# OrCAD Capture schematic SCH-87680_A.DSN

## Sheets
1 4. BRKT-Sensors: size B; title: FRDM-STBA-A8961; rev: A; company: Freescale Semiconductor; note: SCH-87680 PDF: SPF-87680; note: 6501 William Cannon Drive West; note: Austin, TX 78735-8598
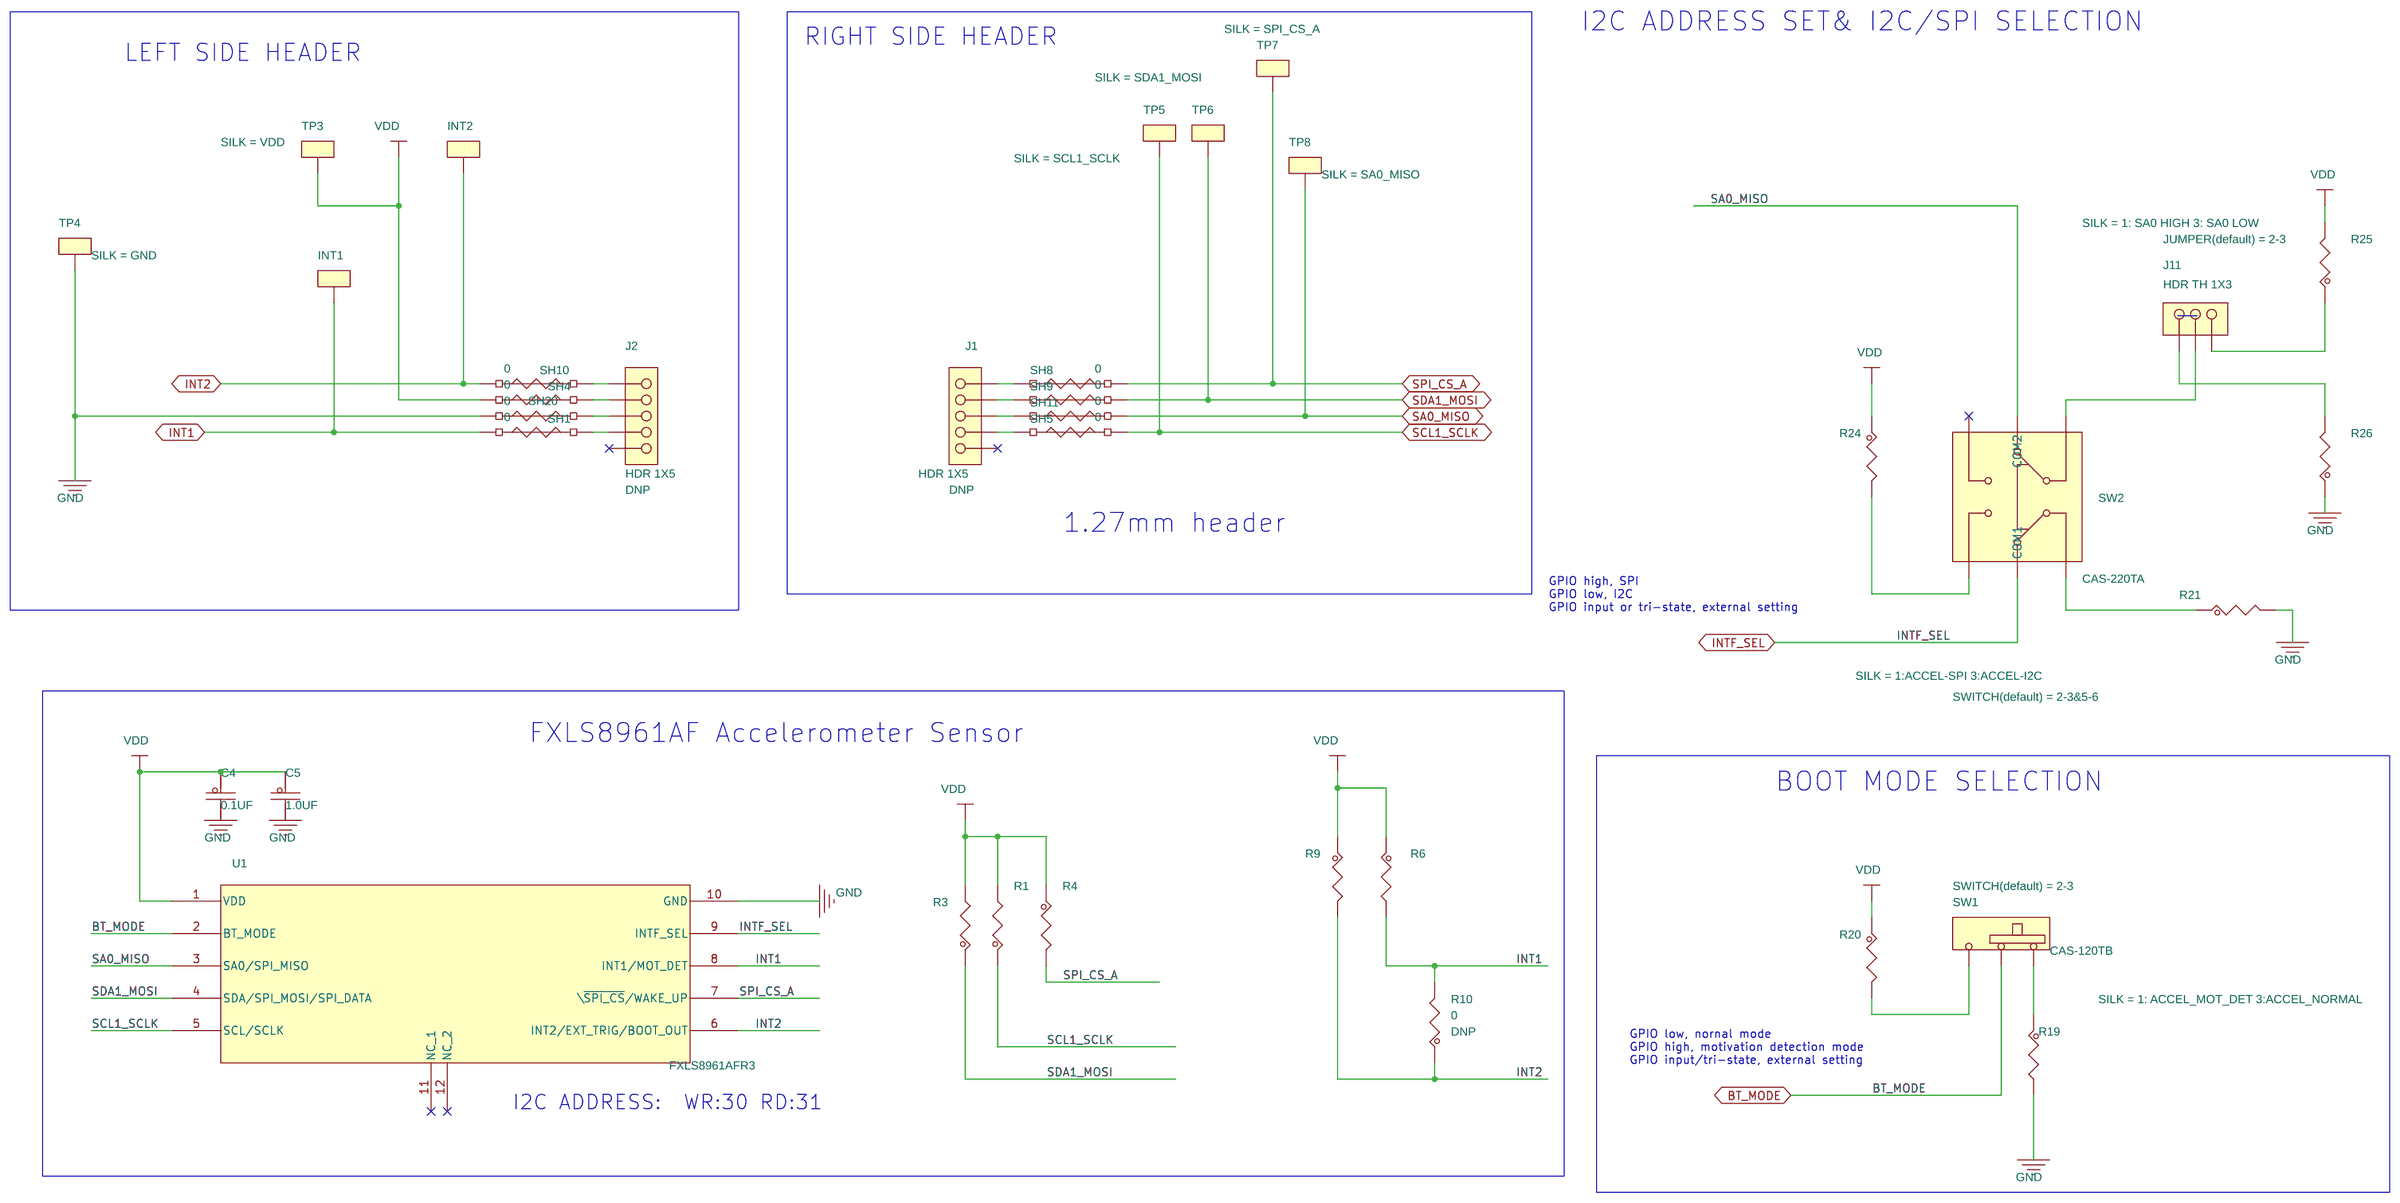
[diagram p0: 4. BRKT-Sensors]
2 1. Title Page: company: NXP Semiconductors
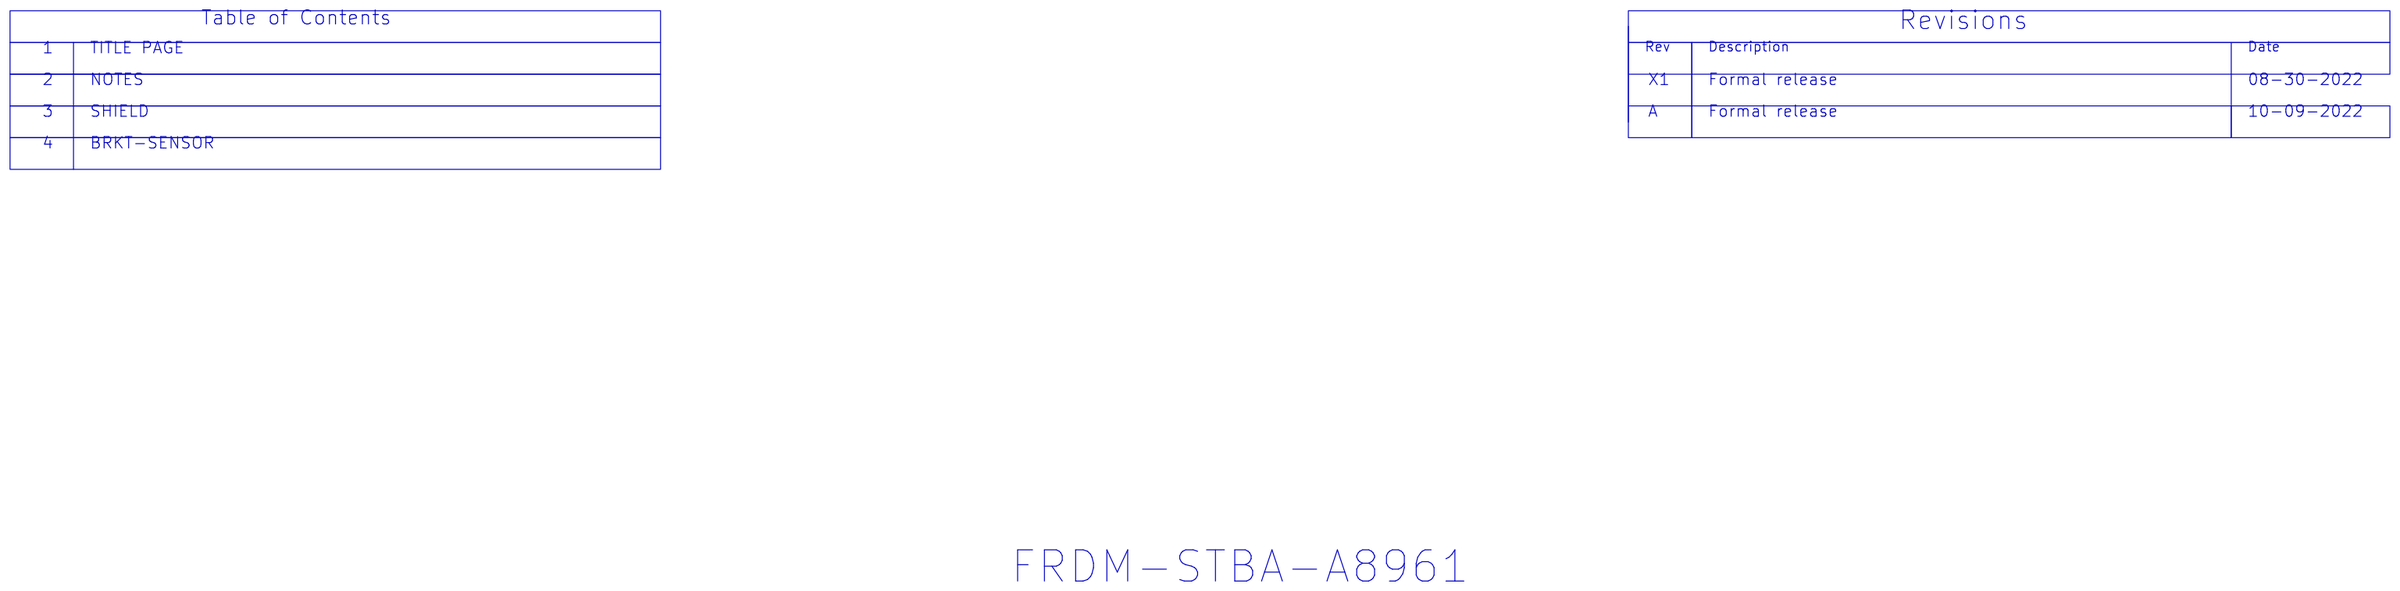
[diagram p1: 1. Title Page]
3 2. Notes
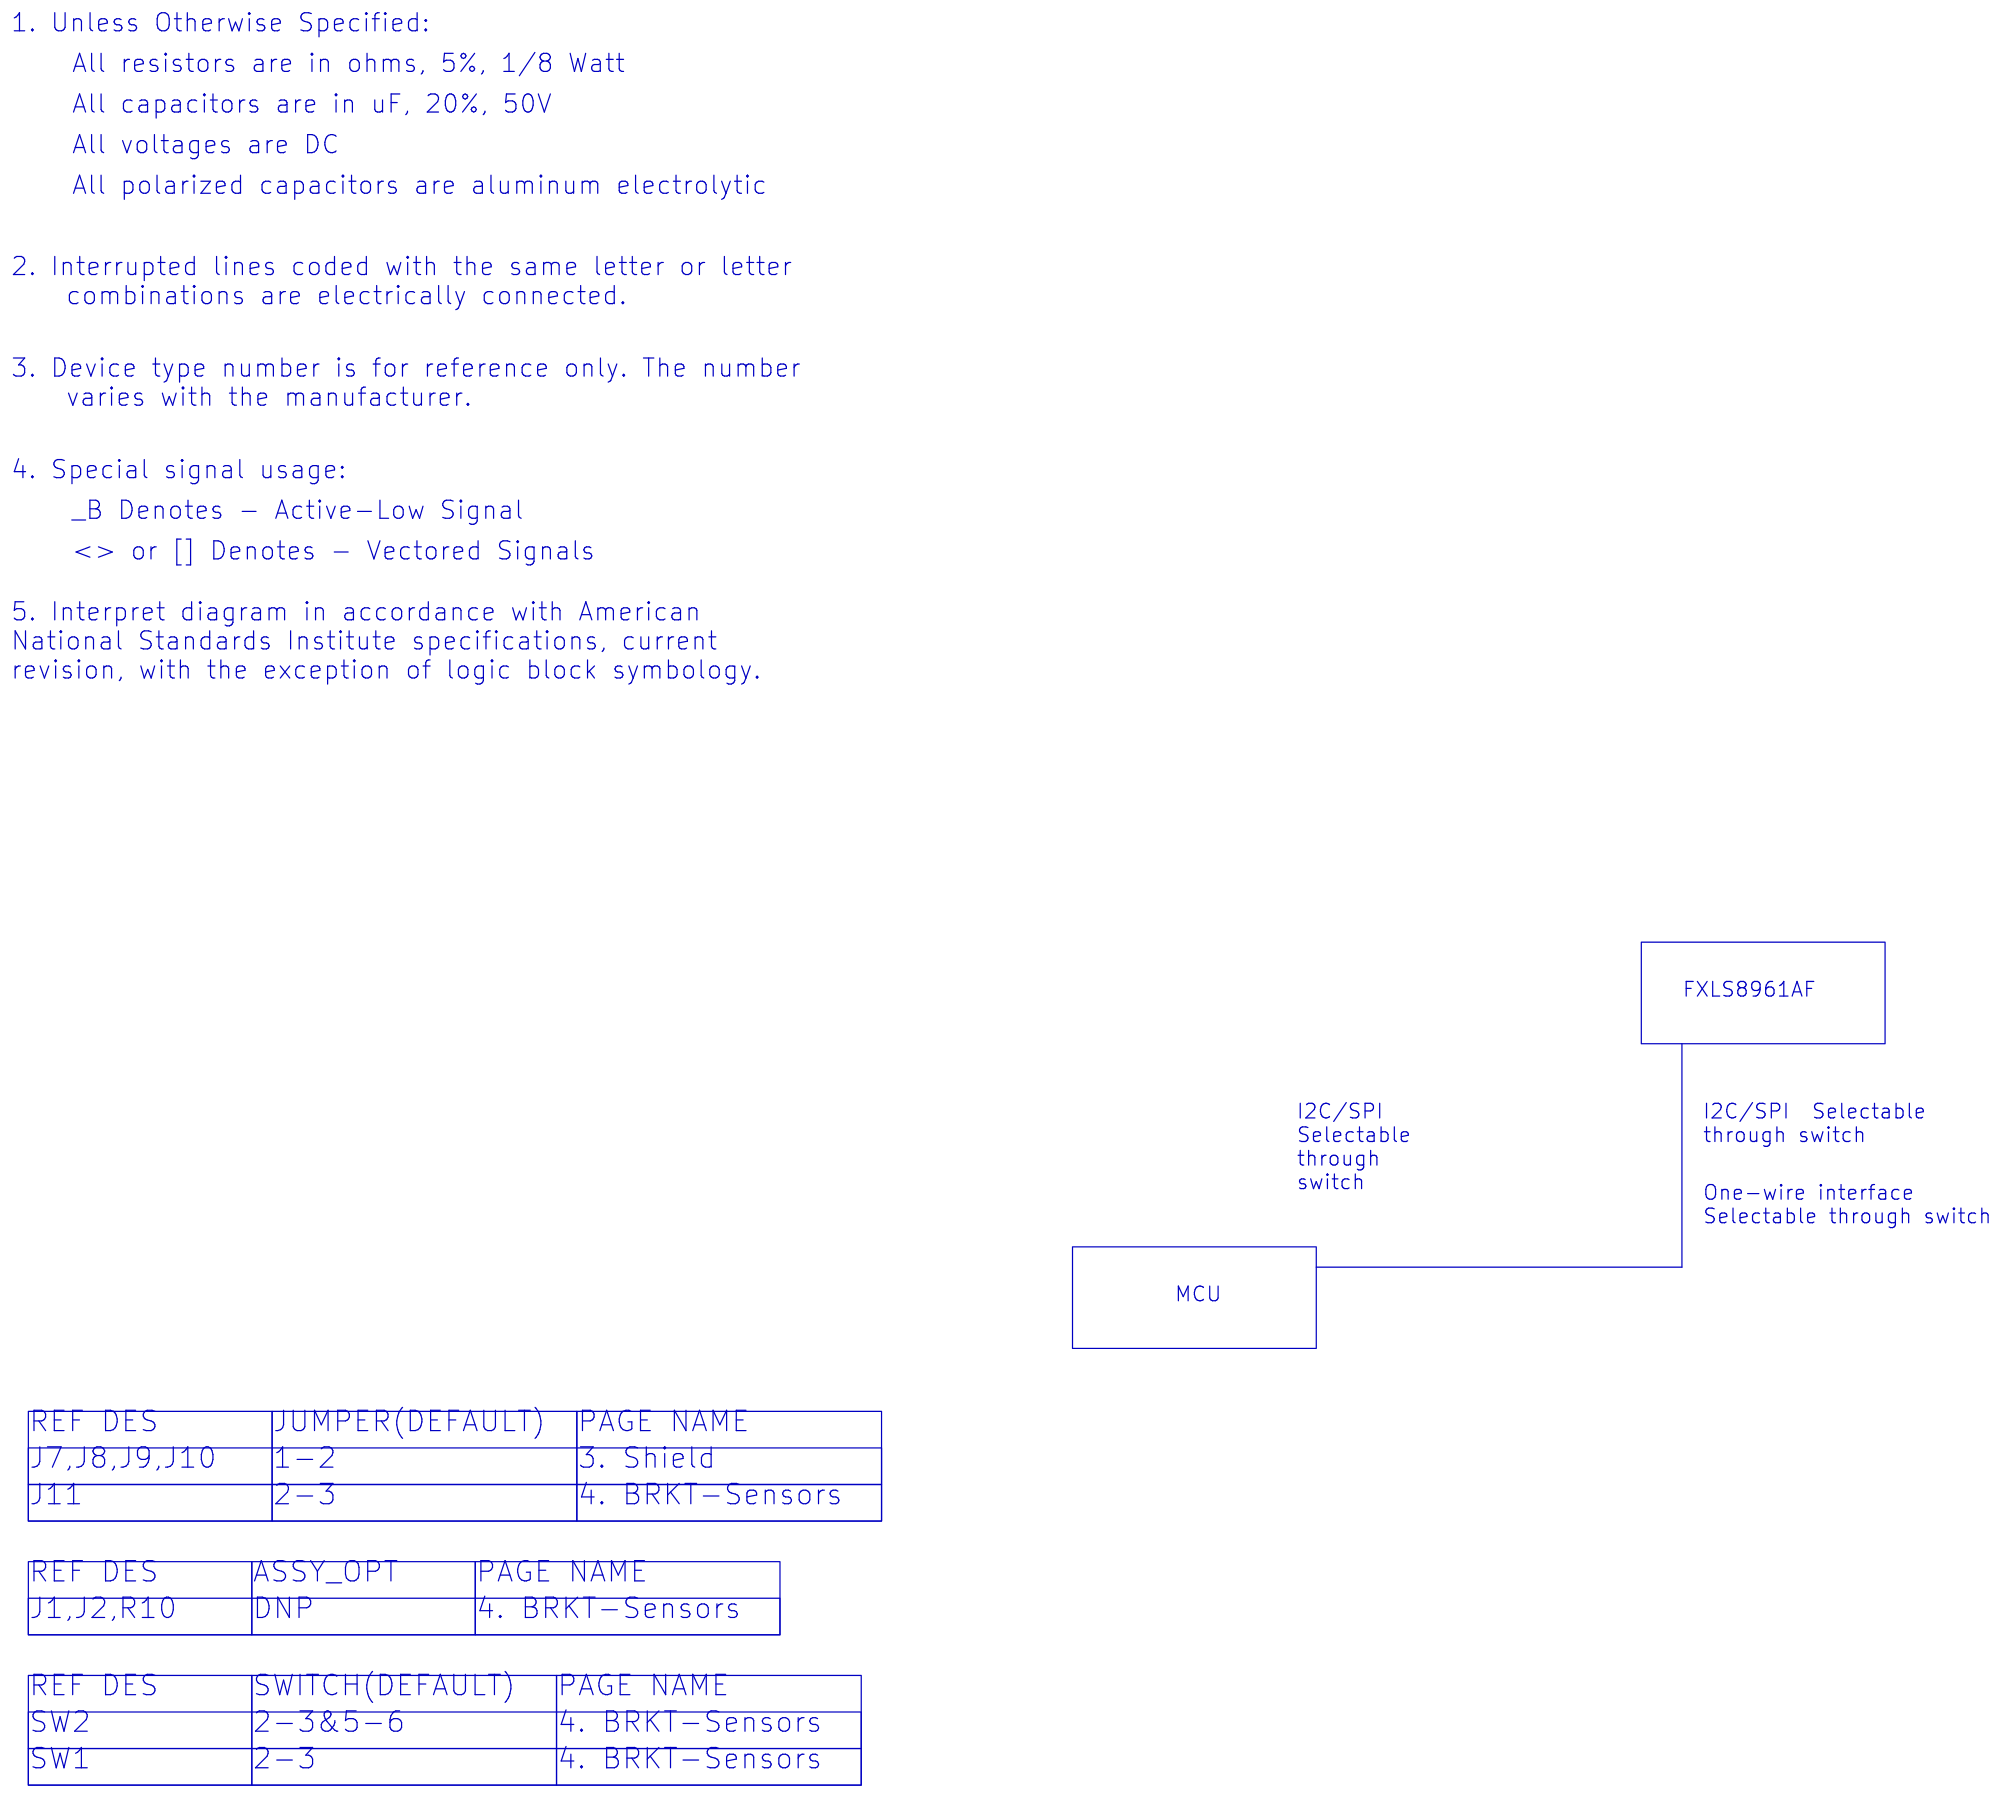
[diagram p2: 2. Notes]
4 3. Shield: size B
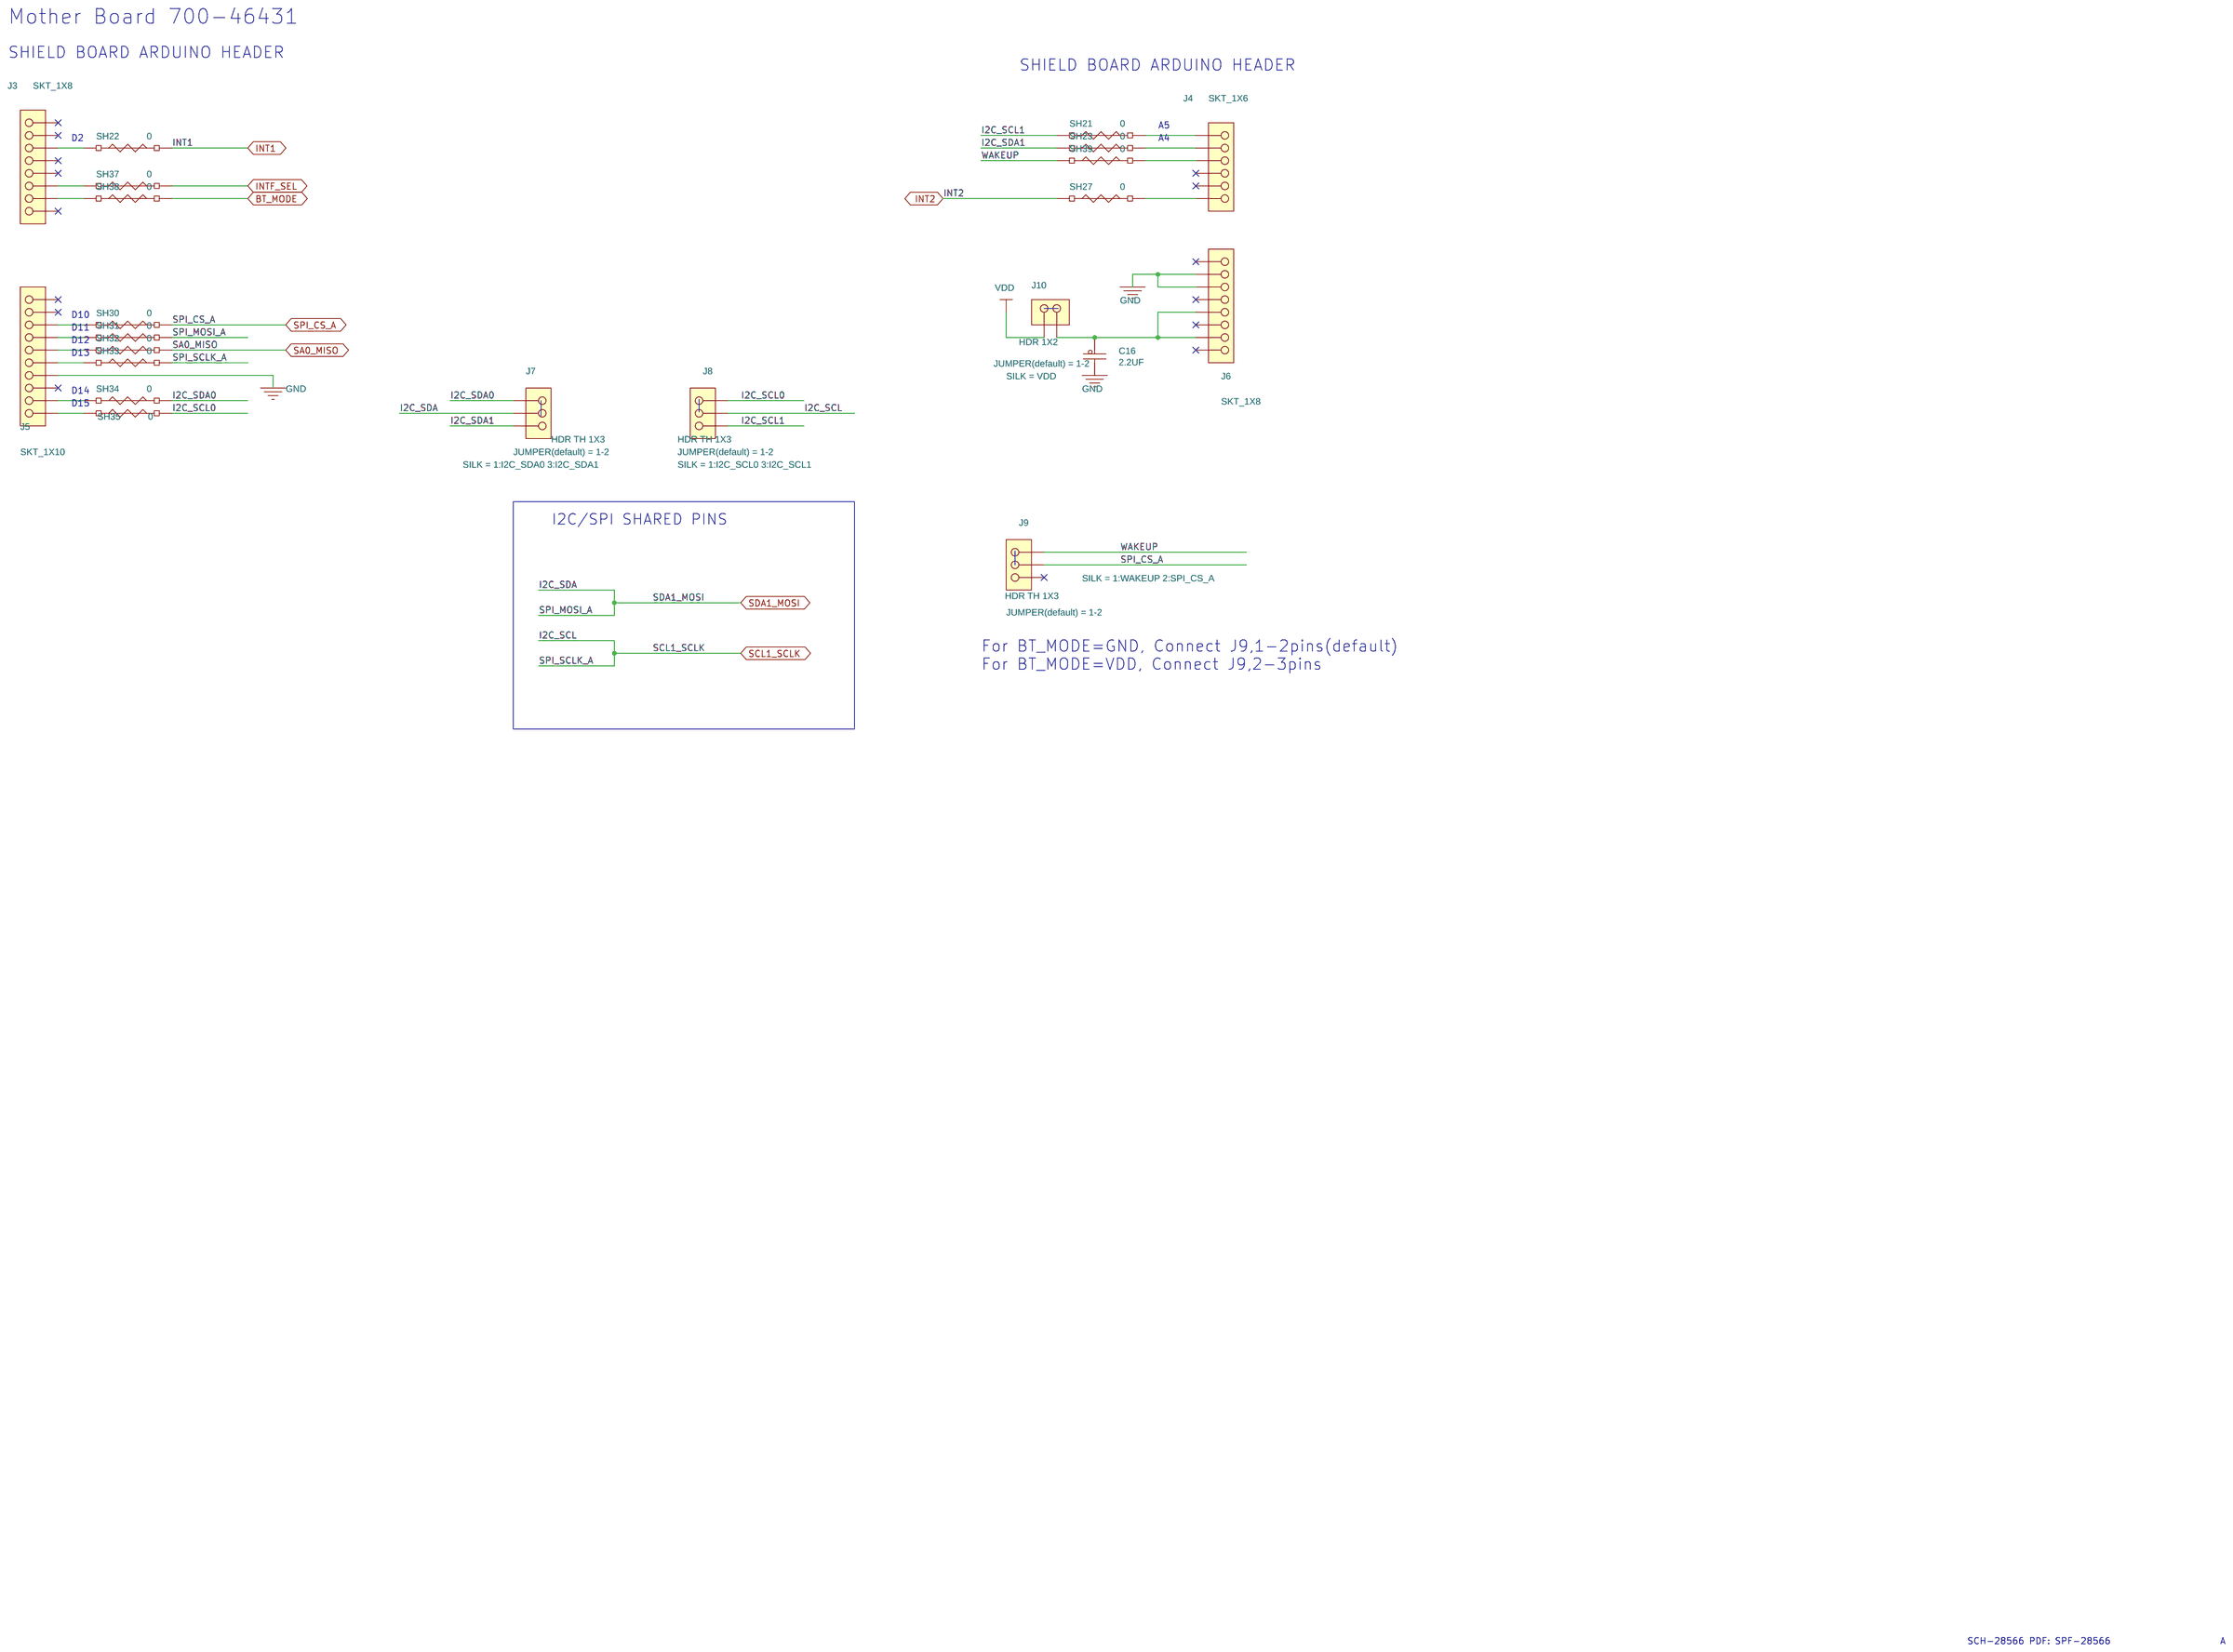
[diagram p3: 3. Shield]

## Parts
sheet 3. Shield
C16  2.2UF  [CC0402_25]
J3  SKT_1X8  [con_skt1x8_th]
J4  SKT_1X6  [con_skt1x6_th]
J5  SKT_1X10  [con_skt1x10_th]
J6  SKT_1X8  [con_skt1x8_th]
J7  HDR TH 1X3  [HDR103]
J8  HDR TH 1X3  [HDR103]
J9  HDR TH 1X3  [HDR103]
J10  HDR 1X2  [hdr1x2_1p27_th]
SH21  0  [SH0201]
SH22  0  [SH0201]
SH23  0  [SH0201]
SH27  0  [SH0201]
SH30  0  [SH0201]
SH31  0  [SH0201]
SH32  0  [SH0201]
SH33  0  [SH0201]
SH34  0  [SH0201]
SH35  0  [SH0201]
SH37  0  [SH0201]
SH38  0  [SH0201]
SH39  0  [SH0201]
sheet 4. BRKT-Sensors
C4  0.1UF  [CC0402_25]
C5  1.0UF  [CC0402_25]
INT1  0805  [testpoint_122x049mil]
INT2  0805  [testpoint_122x049mil]
J1  HDR 1X5  [hdr1x5_50_th]
J2  HDR 1X5  [hdr1x5_50_th]
J11  HDR TH 1X3  [HDR103]
R1  4.7K  [RC0603]
R3  4.7K  [RC0603]
R4  10K  [RC0603]
R6  10K  [RC0603]
R9  10K  [RC0603]
R10  0  [RC0603]
R19  10K  [RC0603]
R20  10K  [RC0603]
R21  10K  [RC0603]
R24  10K  [RC0603]
R25  10K  [RC0603]
R26  10K  [RC0603]
SH1  0  [SH0201]
SH4  0  [SH0201]
SH5  0  [SH0201]
SH8  0  [SH0201]
SH9  0  [SH0201]
SH10  0  [SH0201]
SH11  0  [SH0201]
SH20  0  [SH0201]
SW1  CAS-120TB  [sw3_1p75_3x6]
SW2  CAS-220TA  [sw6_1p75_4x5]
TP3  0805  [testpoint_122x049mil]
TP4  0805  [testpoint_122x049mil]
TP5  0805  [testpoint_122x049mil]
TP6  0805  [testpoint_122x049mil]
TP7  0805  [testpoint_122x049mil]
TP8  0805  [testpoint_122x049mil]
U1  FXLS8961AFR3  [qfn12_0p65_3x3]

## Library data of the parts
C16 = CAP_NP: CAP CER 2.2UF 6.3V 20% X5R 0402; AGILE_PN: 150-76792; CAD_APPROVED: Yes; FPLIST: CC0402_25,CC0402_HD,0402_CC; HEIGHT: 0.55MM; MFG_NAME01: KEMET; MFG_PN01: C0402C225M9PACTU; Package Size: 0402; ROHS: Yes; Rated Voltage: 6.3V; Temp Range: -55C to +85C; Tolerance: 20%; VOLTAGE: 6.3V
J3 J6 = CONN_HDR_8X1: CON 1X8 SKT TH 100MIL SP 340H AU 394L; 3D_Mechanical_Footprint_File: http://fcl.am.freescale.net/ALLEGRO/step/con_skt1x8_th_394l.STEP; AGILE_PN: 210-80359; CAD_APPROVED: Yes; HEIGHT: 8.64MM; MFG_NAME01: SAMTEC; MFG_PN01: SSQ-108-03-F-S; ROHS: Yes; Temp Range: -55°C to +125°C
J4 = CONN_HDR_6X1: CON 1X6 SKT TH 100MIL SP 340H AU 394L; 3D_Mechanical_Footprint_File: http://fcl.am.freescale.net/ALLEGRO/step/con_skt1x6_th_394l.STEP; AGILE_PN: 210-80357; CAD_APPROVED: Yes; HEIGHT: 8.64MM; MFG_NAME01: SAMTEC; MFG_PN01: SSQ-106-03-F-S; ROHS: Yes; Temp Range: -55°C to +125°C
J5 = CONN_HDR_10X1: CON 1X10 SKT TH 100MIL SP 340H AU 394L; 3D_Mechanical_Footprint_File: http://fcl.am.freescale.net/ALLEGRO/step/con_skt1x10_th_394l.STEP; AGILE_PN: 210-80360; CAD_APPROVED: Yes; HEIGHT: 8.64MM; MFG_NAME01: SAMTEC; MFG_PN01: SSQ-110-03-F-S; ROHS: Yes; Temp Range: -55°C to +125°C
J7 = CONN_HDR_3X1: HDR 1x3 TH 100MIL SP 343H AU 100L; 3D_Mechanical_Footprint_File: http://fcl.am.freescale.net/ALLEGRO/step/hdr103.STEP; AGILE_PN: 210-80734; ASSY_NOTE: 2-3; CAD_APPROVED: Yes; HEIGHT: 8.72MM; JUMPER(default): 1-2; MFG_NAME01: SAMTEC; MFG_PN01: TSW-103-07-F-S; ROHS: Yes; SILK: 1:I2C_SDA0 3:I2C_SDA1; Temp Range: -55°C to +125°C
J8 = CONN_HDR_3X1: HDR 1x3 TH 100MIL SP 343H AU 100L; 3D_Mechanical_Footprint_File: http://fcl.am.freescale.net/ALLEGRO/step/hdr103.STEP; AGILE_PN: 210-80734; ASSY_NOTE: 2-3; CAD_APPROVED: Yes; HEIGHT: 8.72MM; JUMPER(default): 1-2; MFG_NAME01: SAMTEC; MFG_PN01: TSW-103-07-F-S; ROHS: Yes; SILK: 1:I2C_SCL0 3:I2C_SCL1; Temp Range: -55°C to +125°C
J9 = CONN_HDR_3X1: HDR 1x3 TH 100MIL SP 343H AU 100L; 3D_Mechanical_Footprint_File: http://fcl.am.freescale.net/ALLEGRO/step/hdr103.STEP; AGILE_PN: 210-80734; CAD_APPROVED: Yes; HEIGHT: 8.72MM; JUMPER(default): 1-2; MFG_NAME01: SAMTEC; MFG_PN01: TSW-103-07-F-S; ROHS: Yes; SILK: 1:WAKEUP 2:SPI_CS_A; Temp Range: -55°C to +125°C
J10 = CONN_HDR_2X1: HDR 1X2 TH 1.27MM SP 205H AU 120L; 3D_Mechanical_Footprint_File: http://fcl.am.freescale.net/ALLEGRO/step/hdr1x2_1p27_th.STEP; AGILE_PN: 210-82802; CAD_APPROVED: Yes; HEIGHT: 5.2MM; JUMPER(default): 1-2; MFG_NAME01: Samtec; MFG_PN01: TMS-102-02-G-S; Package Type: Through Hole; ROHS: Yes; SILK: VDD; Temp Range: -55°C to +125°C
SH1 SH4 SH5 SH8-SH11 SH20-SH23 SH27 SH30-SH35 SH37-SH39 = RES_SHORT-2: ZERO OHM CUT TRACE 0201 PADS; NO PART TO ORDER; AGILE_PN: 470-76473; CAD_APPROVED: Yes; FPLIST: SH0201,SH0201_CC; HEIGHT: 0.1 MM; ROHS: Yes
C4 = CAP_NP: CAP CER 0.1UF 10V 10% X5R 0402; AGILE_PN: 150-75634; CAD_APPROVED: Yes; FPLIST: CC0402_25,CC0402_HD,0402_CC; HEIGHT: 0.64MM; MFG_NAME01: YAGEO AMERICA; MFG_PN01: CC0402KRX5R6BB104; Package Size: 0402; ROHS: Yes; Rated Voltage: 10V; Temp Range: -55C to +85C; Tolerance: 10%; VOLTAGE: 10V
C5 = CAP_NP: CAP CER 1.0UF 10V 10% X5R 0402; AGILE_PN: 150-75772; CAD_APPROVED: Yes; FPLIST: CC0402_25,CC0402_HD,0402_CC; HEIGHT: 0.6MM; MFG_NAME01: YAGEO AMERICA; MFG_PN01: CC0402KRX5R6BB105; Package Size: 0402; ROHS: Yes; Rated Voltage: 10V; Temp Range: -55C to +85C; Tolerance: 10%; VOLTAGE: 10V
INT1 INT2 = TEST_POINT: TEST POINT PAD 3.1MMX1.25MM SMT AEC-Q200 0805; 3D_Mechanical_Footprint_File: http://fcl.am.freescale.net/ALLEGRO/step/testpoint_122x049mil.STEP; AGILE_PN: 211-79608; CAD_APPROVED: Yes; HEIGHT: 1.45MM; MFG_NAME01: KOA SPEER; MFG_PN01: RCTCTE; Package Size: 2X1.25x1.45MM; Package Type: SMT; ROHS: Yes
J1 J2 = CONN_HDR_5X1: HDR 1X5 TH 50MIL SP 159H AU 90L; 3D_Mechanical_Footprint_File: http://fcl.am.freescale.net/ALLEGRO/step/hdr1x5_50_th.STEP; AGILE_PN: 210-82660; ASSY_OPT: DNP; CAD_APPROVED: Yes; HEIGHT: 4.04MM; MFG_NAME01: SAMTEC; MFG_PN01: FTS-105-01-L-S; Package Type: Through Hole; ROHS: Yes; Temp Range: -55°C to +125°C
J11 = CONN_HDR_3X1: HDR 1x3 TH 100MIL SP 343H AU 100L; 3D_Mechanical_Footprint_File: http://fcl.am.freescale.net/ALLEGRO/step/hdr103.STEP; AGILE_PN: 210-80734; CAD_APPROVED: Yes; HEIGHT: 8.72MM; JUMPER(default): 2-3; MFG_NAME01: SAMTEC; MFG_PN01: TSW-103-07-F-S; ROHS: Yes; SILK: 1: SA0 HIGH 3: SA0 LOW; Temp Range: -55°C to +125°C
R1 R3 = RES: RES MF 4.7K 1/10W 5% 0603; AGILE_PN: 470-75414; CAD_APPROVED: Yes; FPLIST: RC0603_OV,RC0603,0603_CC; HEIGHT: 0.55 MM; MFG_NAME01: VISHAY INTERTECHNOLOGY; MFG_PN01: CRCW06034K70JNEA; ROHS: Yes; Tolerance: 5%
R4 R6 R9 R19-R21 R24-R26 = RES: RES MF 10K 1/10W 5% 0603; AGILE_PN: 470-75410; CAD_APPROVED: Yes; FPLIST: RC0603_OV,RC0603,0603_CC; HEIGHT: 0.55MM; MFG_NAME01: BOURNS; MFG_PN01: CR0603-JW-103ELF; ROHS: Yes; Temp Range: –55 °C to +155 °C; Tolerance: 5%
R10 = RES: RES MF ZERO OHM 1/10W 1% 0603; AGILE_PN: 470-80217; ASSY_OPT: DNP; CAD_APPROVED: Yes; FPLIST: RC0603_OV,RC0603,R603-X2,0603_CC; HEIGHT: 0.55 MM; MFG_NAME01: MULTICOMP; MFG_PN01: MC0603SAF0000T5E; ROHS: Yes; Tolerance: 1%
SW1 = SW3_SPDT_SLD: SW SPDT SLD 100MA 6V SMD; 3D_Mechanical_Footprint_File: http://fcl.am.freescale.net/ALLEGRO/step/sw3_1p75_3x6.STEP; AGILE_PN: 510-78101; ASSY_NOTE: 2-3; CAD_APPROVED: Yes; HEIGHT: 2.5MM; MFG_NAME01: NIDEC COPAL ELECTRONICS CORP; ROHS: Yes; SILK: 1: ACCEL_MOT_DET 3:ACCEL_NORMAL; SWITCH(default): 2-3
SW2 = SW_SL_DPDT_6P: SW DPDT SLIDE 24VDC 25mA SMD; 3D_Mechanical_Footprint_File: http://fcl.am.freescale.net/ALLEGRO/step/sw6_1p75_4x5.step; AGILE_PN: 510-78098; CAD_APPROVED: Yes; HEIGHT: 2.5MM; MFG_NAME01: NIDEC COPAL ELECTRONICS CORP; ROHS: Yes; SILK: 1:ACCEL-SPI 3:ACCEL-I2C; SWITCH(default): 2-3&5-6; Temp Range: -40 to +85&#8451;; Temp_Range: -40 to +85&#8451;
TP3 = TEST_POINT: TEST POINT PAD 3.1MMX1.25MM SMT AEC-Q200 0805; 3D_Mechanical_Footprint_File: http://fcl.am.freescale.net/ALLEGRO/step/testpoint_122x049mil.STEP; AGILE_PN: 211-79608; CAD_APPROVED: Yes; HEIGHT: 1.45MM; MFG_NAME01: KOA SPEER; MFG_PN01: RCTCTE; Package Size: 2X1.25x1.45MM; Package Type: SMT; ROHS: Yes; SILK: VDD
TP4 = TEST_POINT: TEST POINT PAD 3.1MMX1.25MM SMT AEC-Q200 0805; 3D_Mechanical_Footprint_File: http://fcl.am.freescale.net/ALLEGRO/step/testpoint_122x049mil.STEP; AGILE_PN: 211-79608; CAD_APPROVED: Yes; HEIGHT: 1.45MM; MFG_NAME01: KOA SPEER; MFG_PN01: RCTCTE; Package Size: 2X1.25x1.45MM; Package Type: SMT; ROHS: Yes; SILK: GND
TP5 = TEST_POINT: TEST POINT PAD 3.1MMX1.25MM SMT AEC-Q200 0805; 3D_Mechanical_Footprint_File: http://fcl.am.freescale.net/ALLEGRO/step/testpoint_122x049mil.STEP; AGILE_PN: 211-79608; CAD_APPROVED: Yes; HEIGHT: 1.45MM; MFG_NAME01: KOA SPEER; MFG_PN01: RCTCTE; Package Size: 2X1.25x1.45MM; Package Type: SMT; ROHS: Yes; SILK: SCL1_SCLK
TP6 = TEST_POINT: TEST POINT PAD 3.1MMX1.25MM SMT AEC-Q200 0805; 3D_Mechanical_Footprint_File: http://fcl.am.freescale.net/ALLEGRO/step/testpoint_122x049mil.STEP; AGILE_PN: 211-79608; CAD_APPROVED: Yes; HEIGHT: 1.45MM; MFG_NAME01: KOA SPEER; MFG_PN01: RCTCTE; Package Size: 2X1.25x1.45MM; Package Type: SMT; ROHS: Yes; SILK: SDA1_MOSI
TP7 = TEST_POINT: TEST POINT PAD 3.1MMX1.25MM SMT AEC-Q200 0805; 3D_Mechanical_Footprint_File: http://fcl.am.freescale.net/ALLEGRO/step/testpoint_122x049mil.STEP; AGILE_PN: 211-79608; CAD_APPROVED: Yes; HEIGHT: 1.45MM; MFG_NAME01: KOA SPEER; MFG_PN01: RCTCTE; Package Size: 2X1.25x1.45MM; Package Type: SMT; ROHS: Yes; SILK: SPI_CS_A
TP8 = TEST_POINT: TEST POINT PAD 3.1MMX1.25MM SMT AEC-Q200 0805; 3D_Mechanical_Footprint_File: http://fcl.am.freescale.net/ALLEGRO/step/testpoint_122x049mil.STEP; AGILE_PN: 211-79608; CAD_APPROVED: Yes; HEIGHT: 1.45MM; MFG_NAME01: KOA SPEER; MFG_PN01: RCTCTE; Package Size: 2X1.25x1.45MM; Package Type: SMT; ROHS: Yes; SILK: SA0_MISO
U1 = FXLS8961AFR3_QFN12: IC ACCELEROMETER 3-AXIS QFN12; AGILE_PN: TMP-CIP-10975; CAD_APPROVED: Yes; HEIGHT: 1.3 MM; MFG_NAME01: NXP_SEMICONDUCTORS; PRE_APN: 312-83567; Package Size: 3mmx3mmx1mm; ROHS: Yes

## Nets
GND: C4.2 C5.2 C16.2 J5.7 J6.6 J6.7 R19.2 R21.2 R26.1 SH20.2 TP4.1 U1.10(GND)
VDD: C4.1 C5.1 J10.1 R1.2 R3.2 R4.1 R6.1 R9.1 R20.1 R24.1 R25.2 SH4.2 TP3.1 U1.1(VDD)
BT_MODE: SH38.2 SW1.2 U1.2(BT_MODE)
I2C_SCL0: J8.1 SH35.2
I2C_SCL1: J8.3 SH21.1
I2C_SDA0: J7.1 SH34.2
I2C_SDA1: J7.3 SH23.1
INT1: INT1.1 R6.2 R10.2 SH1.2 SH22.2 U1.8(INT1/MOT_DET)
INT2: INT2.1 R9.2 R10.1 SH10.2 SH27.1 U1.6(INT2/EXT_TRIG/BOOT_OUT)
INTF_SEL: SH37.2 SW2.2(COM1) U1.9(INTF_SEL)
SA0_MISO: SH11.2 SH32.2 SW2.5(COM2) TP8.1 U1.3(SA0/SPI_MISO)
SCL1_SCLK: J8.2 R1.1 SH5.2 SH33.2 TP5.1 U1.5(SCL/SCLK)
SDA1_MOSI: J7.2 R3.1 SH9.2 SH31.2 TP6.1 U1.4(SDA/SPI_MOSI/SPI_DATA)
SPI_CS_A: J9.2 R4.2 SH8.2 SH30.2 TP7.1 U1.7(\~{SPI_CS}/WAKE_UP)
WAKEUP: J9.1 SH39.1
N00622: J5.9 SH34.1
N00628: J5.10 SH35.1
N00993: C16.1 J6.2 J6.4 J10.2
N05692: J4.6 SH21.2
N05729: J4.5 SH23.2
N16652859: J5.4 SH31.1
N16652885: J5.5 SH32.1
N16652889: J5.6 SH33.1
N16653001: J5.3 SH30.1
N16659634: J4.1 SH27.2
N16701284: J3.3 SH22.1
N16711839: J2.1 SH10.1
N16711841: J2.2 SH4.1
N16711843: J2.3 SH20.1
N16711845: J2.4 SH1.1
N16711871: J1.1 SH8.1
N16711873: J1.2 SH9.1
N16711875: J1.3 SH11.1
N16711877: J1.4 SH5.1
N16715705: R20.2 SW1.1
N16718521: R21.1 SW2.3
N16718681: R24.2 SW2.1
N16720544: J3.6 SH37.1
N16720548: J3.7 SH38.1
N16721741: J4.4 SH39.2
N16750160: J11.2 SW2.6
N16750243: J11.1 R25.1
N16750529: J11.3 R26.2
N16884640: R19.1 SW1.3

Not connected (* = marked no-connect by the designer): J1 5*; J2 5*; J3 1* 2* 4* 5* 8*; J4 2* 3*; J5 1* 2* 8*; J6 1* 3* 5* 8*; J9 3*; SW2 4*; U1 11(NC_1)* 12(NC_2)*

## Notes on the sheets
sheet 1
- I2C ADDRESS SET& I2C/SPI SELECTION
- RIGHT SIDE HEADER
- LEFT SIDE HEADER
- 1.27mm header
- GPIO high, SPI
  GPIO low, I2C
  GPIO input or tri-state, external setting
- FXLS8961AF Accelerometer Sensor
- BOOT MODE SELECTION
- GPIO low, nornal mode
  GPIO high, motivation detection mode
  GPIO input/tri-state, external setting
- I2C ADDRESS:  WR:30 RD:31
sheet 2
- Table of Contents
- Revisions
- 1
- TITLE PAGE
- Rev
- Description
- Date
- 2
- NOTES
- X1
- Formal release
- 08-30-2022
- 3
- SHIELD
- A
- Formal release
- 10-09-2022
- 4
- BRKT-SENSOR
- FRDM-STBA-A8961
sheet 3
- 1. Unless Otherwise Specified:
- All resistors are in ohms, 5%, 1/8 Watt
- All capacitors are in uF, 20%, 50V
- All voltages are DC
- All polarized capacitors are aluminum electrolytic
- 2. Interrupted lines coded with the same letter or letter
      combinations are electrically connected.
- 3. Device type number is for reference only. The number
      varies with the manufacturer.
- 4. Special signal usage:
- _B Denotes - Active-Low Signal
- <> or [] Denotes - Vectored Signals
- 5. Interpret diagram in accordance with American
  National Standards Institute specifications, current
  revision, with the exception of logic block symbology.
- FXLS8961AF
- I2C/SPI
  Selectable
  through
  switch
- I2C/SPI  Selectable
  through switch
- One-wire interface
  Selectable through switch
- MCU
- REF DES
- JUMPER(DEFAULT)
- PAGE NAME
- J7,J8,J9,J10
- 1-2
- 3. Shield
- J11
- 2-3
- 4. BRKT-Sensors
- REF DES
- ASSY_OPT
- PAGE NAME
- J1,J2,R10
- DNP
- 4. BRKT-Sensors
- REF DES
- SWITCH(DEFAULT)
- PAGE NAME
- SW2
- 2-3&5-6
- 4. BRKT-Sensors
- SW1
- 2-3
- 4. BRKT-Sensors
sheet 4
- Mother Board 700-46431
- SHIELD BOARD ARDUINO HEADER
- SHIELD BOARD ARDUINO HEADER
- A5
- D2
- A4
- D10
- D11
- D12
- D13
- D14
- D15
- I2C/SPI SHARED PINS
- For BT_MODE=GND, Connect J9,1-2pins(default)
  For BT_MODE=VDD, Connect J9,2-3pins
- SCH-28566 PDF: SPF-28566
- A
